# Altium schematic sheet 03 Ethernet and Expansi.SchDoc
size 420 x 297 mm; DocumentNumber: 3; SheetNumber: 3; SheetTotal: 12
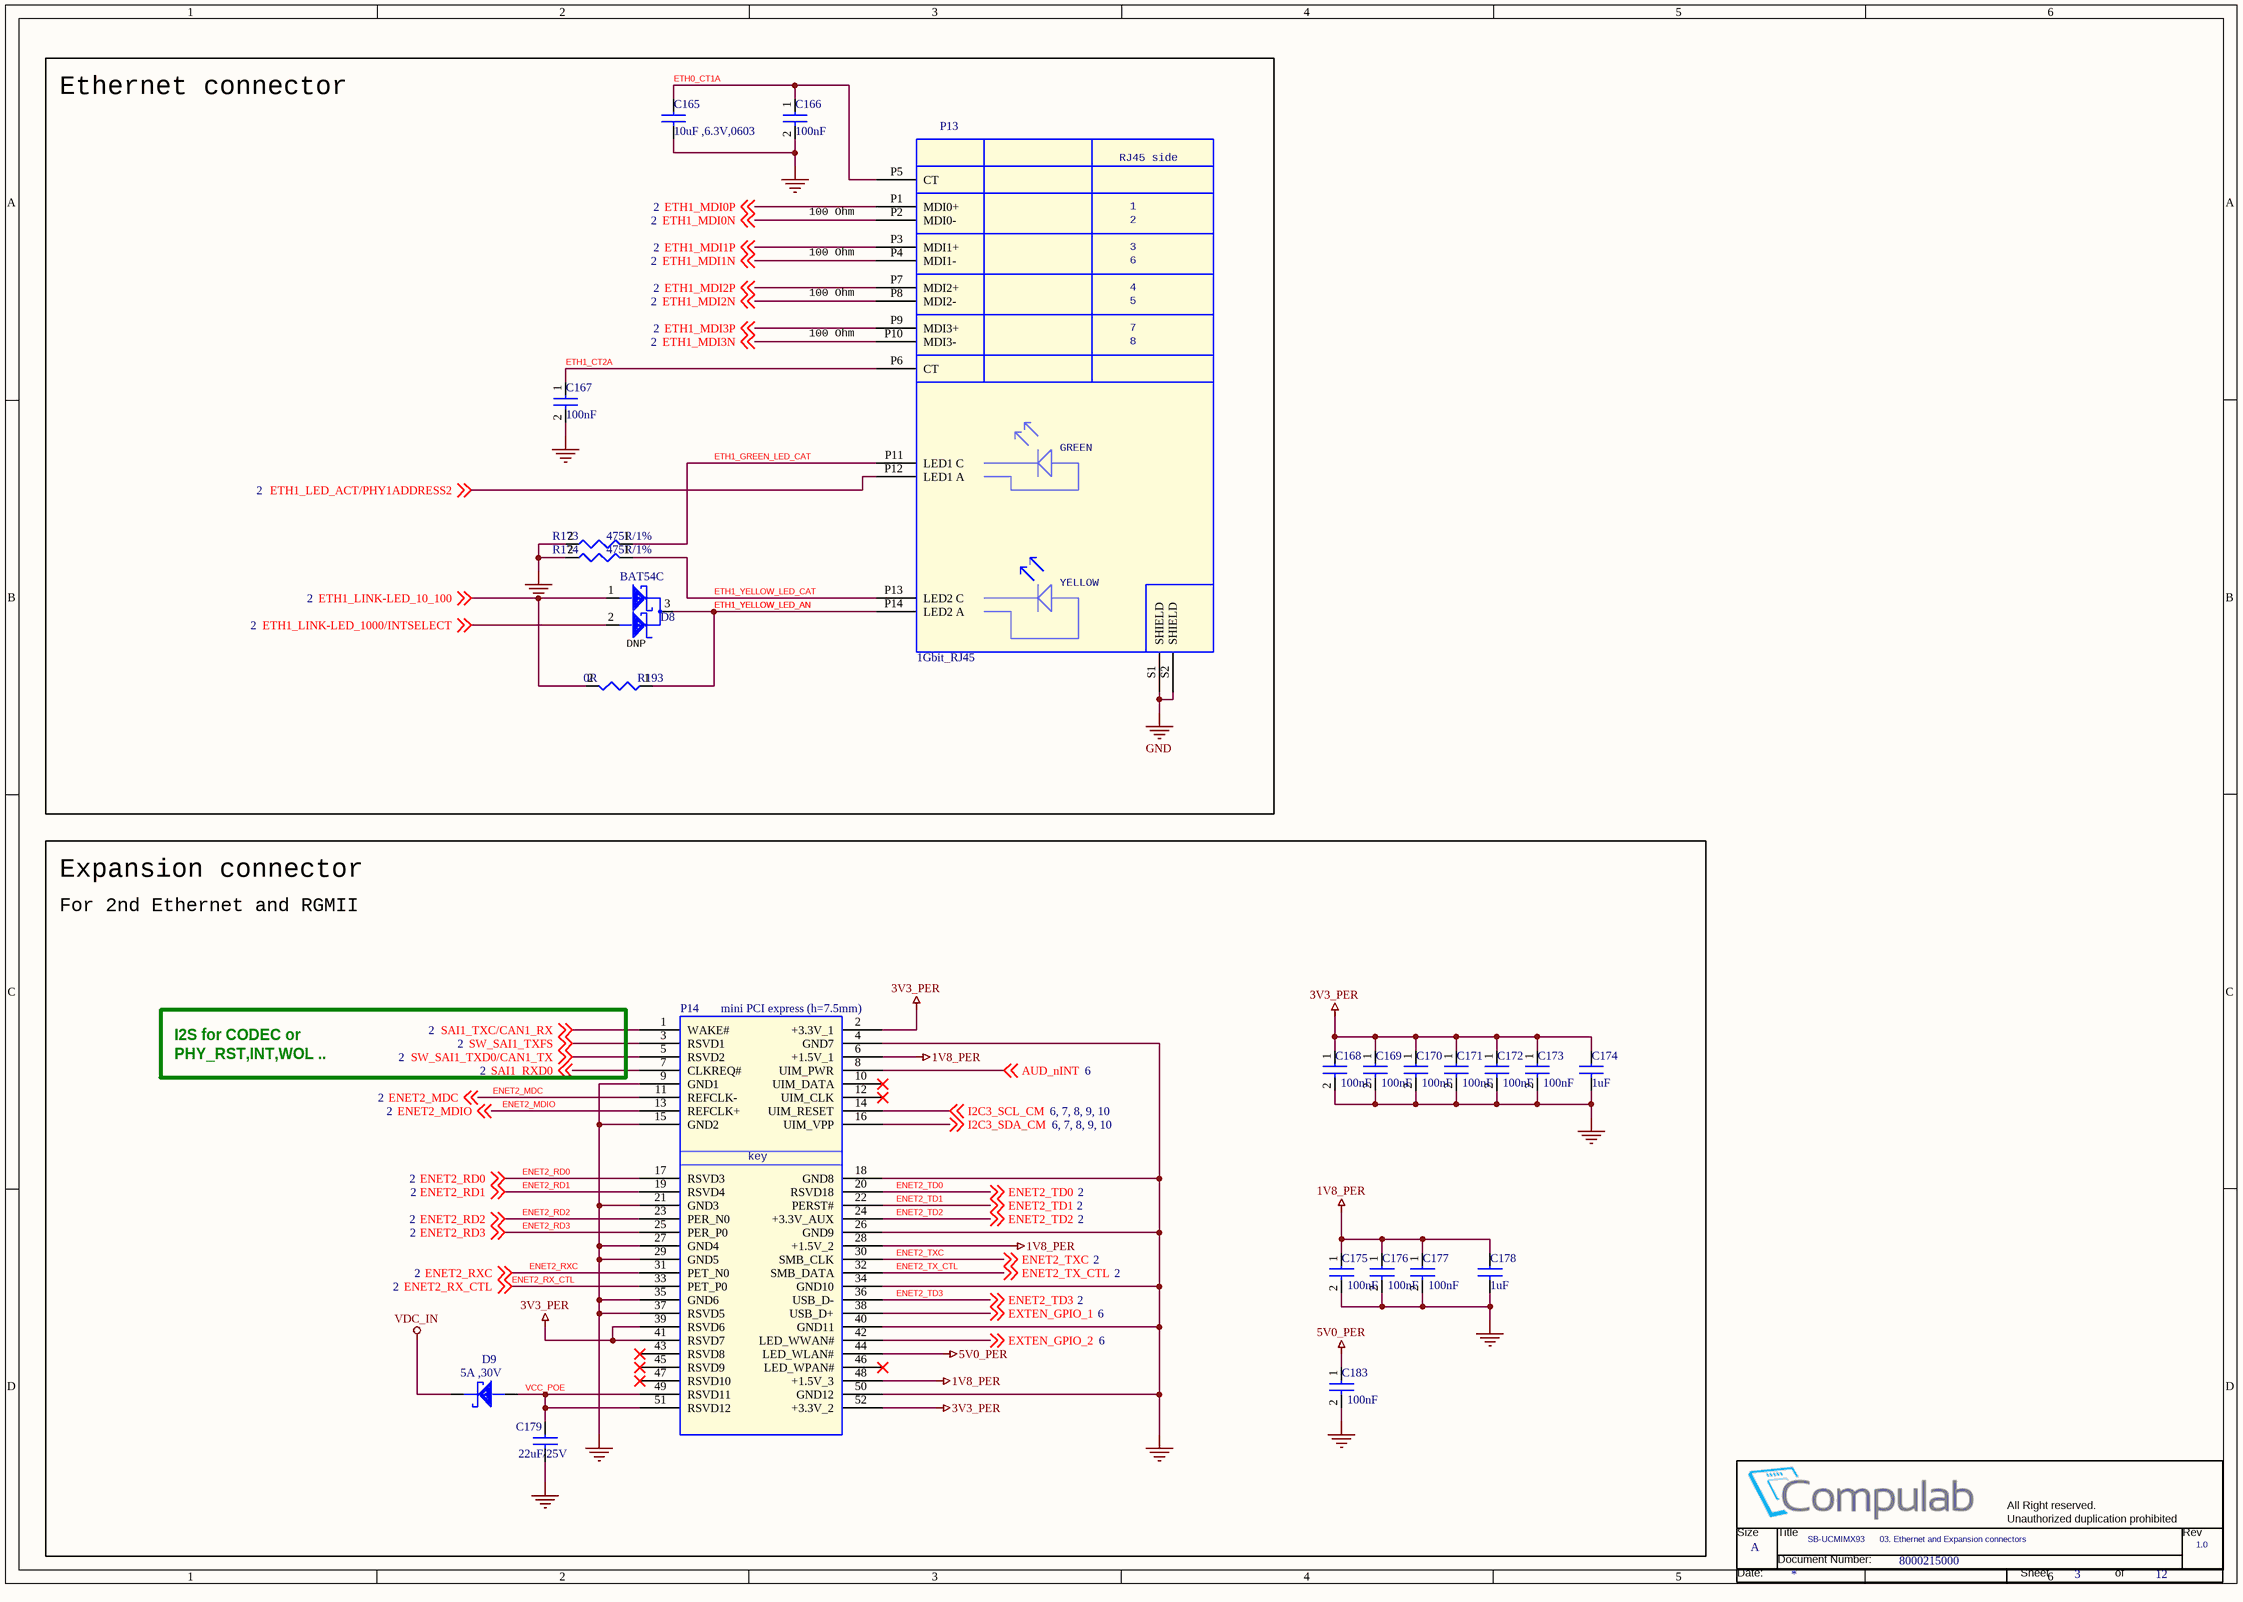
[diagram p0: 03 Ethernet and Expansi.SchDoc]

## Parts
*  Title: SB-UCMIMX93      03. Ethernet and Expansion connectors  Doc: 8000215000  RevCode: 1.0  Page Size: A  Page Number: 3  Page Count: 12  (hidden comment: CompuLabTitleBlk)  (graphical)
C165  10uF ,6.3V,0603  [RC0603]
C166  100nF  [RC0402]
C167  100nF  [RC0402]
C168  100nF  [RC0402]
C169  100nF  [RC0402]
C170  100nF  [RC0402]
C171  100nF  [RC0402]
C172  100nF  [RC0402]
C173  100nF  [RC0402]
C174  1uF  [RC0402]
C175  100nF  [RC0402]
C176  100nF  [RC0402]
C177  100nF  [RC0402]
C178  1uF  [RC0402]
C179  22uF/25V  [C0805]
C183  100nF  [RC0402]
D8  BAT54C  [SOT23]
D9  5A ,30V  [SOD-128]
P13  1Gbit_RJ45  [DUSBRJ-1G]
P14  mini PCI express (h=7.5mm)  [MINIPCIE-4]
R173  475R/1%  [RC0402]
R174  475R/1%  [RC0402]
R193  0R  [RC0402]

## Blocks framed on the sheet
Ethernet connector: C165-C167 D8 P13 R173 R174 R193
Expansion connector: C168-C179 C183 D9 P14

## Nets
1V8_PER: C175.1 C176.1 C177.1 C178.1 P14.6(+1.5V_1) P14.28(+1.5V_2) P14.48(+1.5V_3)
3V3_PER: C168.1 C169.1 C170.1 C171.1 C172.1 C173.1 C174.1 P14.2(+3.3V_1) P14.39(RSVD6) P14.41(RSVD7) P14.52(+3.3V_2)
5V0_PER: C183.1 P14.44(LED_WLAN#)
GND: C165.2 C166.2 C167.2 C168.2 C169.2 C170.2 C171.2 C172.2 C173.2 C174.2 C175.2 C176.2 C177.2 C178.2 C179.2 C183.2 P13.S1(SHIELD) P13.S2(SHIELD) P14.4(GND7) P14.9(GND1) P14.15(GND2) P14.18(GND8) P14.21(GND3) P14.26(GND9) P14.27(GND4) P14.29(GND5) P14.34(GND10) P14.35(GND6) P14.37(RSVD5) P14.40(GND11) P14.50(GND12) R173.2 R174.2
VDC_IN: D9.CATHODE
AUD_nINT: P14.8(UIM_PWR) ; off-sheet AUD_nINT
ENET2_MDC: P14.11(REFCLK-) ; off-sheet ENET2_MDC
ENET2_MDIO: P14.13(REFCLK+) ; off-sheet ENET2_MDIO
ENET2_RD0: P14.17(RSVD3) ; off-sheet ENET2_RD0
ENET2_RD1: P14.19(RSVD4) ; off-sheet ENET2_RD1
ENET2_RD2: P14.23(PER_N0) ; off-sheet ENET2_RD2
ENET2_RD3: P14.25(PER_P0) ; off-sheet ENET2_RD3
ENET2_RX_CTL: P14.33(PET_P0) ; off-sheet ENET2_RX_CTL
ENET2_RXC: P14.31(PET_N0) ; off-sheet ENET2_RXC
ENET2_TD0: P14.20(RSVD18) ; off-sheet ENET2_TD0
ENET2_TD1: P14.22(PERST#) ; off-sheet ENET2_TD1
ENET2_TD2: P14.24(+3.3V_AUX) ; off-sheet ENET2_TD2
ENET2_TD3: P14.36(USB_D-) ; off-sheet ENET2_TD3
ENET2_TX_CTL: P14.32(SMB_DATA) ; off-sheet ENET2_TX_CTL
ENET2_TXC: P14.30(SMB_CLK) ; off-sheet ENET2_TXC
ETH0_CT1A: C165.1 C166.1 P13.P5(CT)
ETH1_CT2A: C167.1 P13.P6(CT)
ETH1_GREEN_LED_CAT: P13.P11(LED1_C) R173.1
ETH1_LED_ACT/PHY1ADDRESS2: P13.P12(LED1_A) ; off-sheet ETH1_LED_ACT/PHY1ADDRESS2
ETH1_LINK-LED_10_100: D8.1(ANODE1) R193.2 ; off-sheet ETH1_LINK-LED_10_100
ETH1_LINK-LED_1000/INTSELECT: D8.2(ANODE2) ; off-sheet ETH1_LINK-LED_1000/INTSELECT
ETH1_MDI0N: P13.P2(MDI0-) ; off-sheet ETH1_MDI0N
ETH1_MDI0P: P13.P1(MDI0+) ; off-sheet ETH1_MDI0P
ETH1_MDI1N: P13.P4(MDI1-) ; off-sheet ETH1_MDI1N
ETH1_MDI1P: P13.P3(MDI1+) ; off-sheet ETH1_MDI1P
ETH1_MDI2N: P13.P8(MDI2-) ; off-sheet ETH1_MDI2N
ETH1_MDI2P: P13.P7(MDI2+) ; off-sheet ETH1_MDI2P
ETH1_MDI3N: P13.P10(MDI3-) ; off-sheet ETH1_MDI3N
ETH1_MDI3P: P13.P9(MDI3+) ; off-sheet ETH1_MDI3P
ETH1_YELLOW_LED_AN: D8.3(CATHODE) P13.P14(LED2_A) R193.1
ETH1_YELLOW_LED_CAT: P13.P13(LED2_C) R174.1
EXTEN_GPIO_1: P14.38(USB_D+) ; off-sheet EXTEN_GPIO_1
EXTEN_GPIO_2: P14.42(LED_WWAN#) ; off-sheet EXTEN_GPIO_2
I2C3_SCL_CM: P14.14(UIM_RESET) ; off-sheet I2C3_SCL_CM
I2C3_SDA_CM: P14.16(UIM_VPP) ; off-sheet I2C3_SDA_CM
SAI1_RXD0: P14.7(CLKREQ#) ; off-sheet SAI1_RXD0
SAI1_TXC/CAN1_RX: P14.1(WAKE#) ; off-sheet SAI1_TXC/CAN1_RX
SW_SAI1_TXD0/CAN1_TX: P14.5(RSVD2) ; off-sheet SW_SAI1_TXD0/CAN1_TX
SW_SAI1_TXFS: P14.3(RSVD1) ; off-sheet SW_SAI1_TXFS
VCC_POE: C179.1 D9.ANODE P14.49(RSVD11) P14.51(RSVD12)

Not connected (* = marked no-connect by the designer): P14 10(UIM_DATA)* 12(UIM_CLK)* 43(RSVD8)* 45(RSVD9)* 46(LED_WPAN#)* 47(RSVD10)*

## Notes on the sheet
- 100 Ohm
- (near D8) DNP
- For 2nd Ethernet and RGMII
- I2S for CODEC or
  PHY_RST,INT,WOL ..

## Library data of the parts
C165 = Cap.,10uF,6.3V,0603,X5R: P/N: 151B10610S
C166-C173 C175-C177 C183 = 100nF, 10V, X7R, 10%, 0402_Dup1: P/N: 151B10400S
C174 C178 = 1uF,X5R,6.3V,0402: P/N: 151B10500S
C179 = Cap.,22uF,25V, 0805: P/N: 151C22620S
D8 = BAT54C: P/N: 130E05400S; CLABCONF0: DNP
D9 = Diode Shotky,5A,30V: P/N: 130E30001S
P13 = Con_0.,1GBit RJ45, short: P/N: 182K01600
P14 = mini PCIe_0: P/N: 182K05202S
R173 R174 = 475R/1%, 0402: P/N: 161C47501S
R193 = 0R, 0402_1: P/N: 161C00005S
